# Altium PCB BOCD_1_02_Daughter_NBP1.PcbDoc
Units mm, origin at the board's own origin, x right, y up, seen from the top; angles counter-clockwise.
Board outline 69 x 80.99 mm, 2 copper layers (Top Layer, Bottom Layer); 48 components, 166 nets, 518 pads, 189 vias.
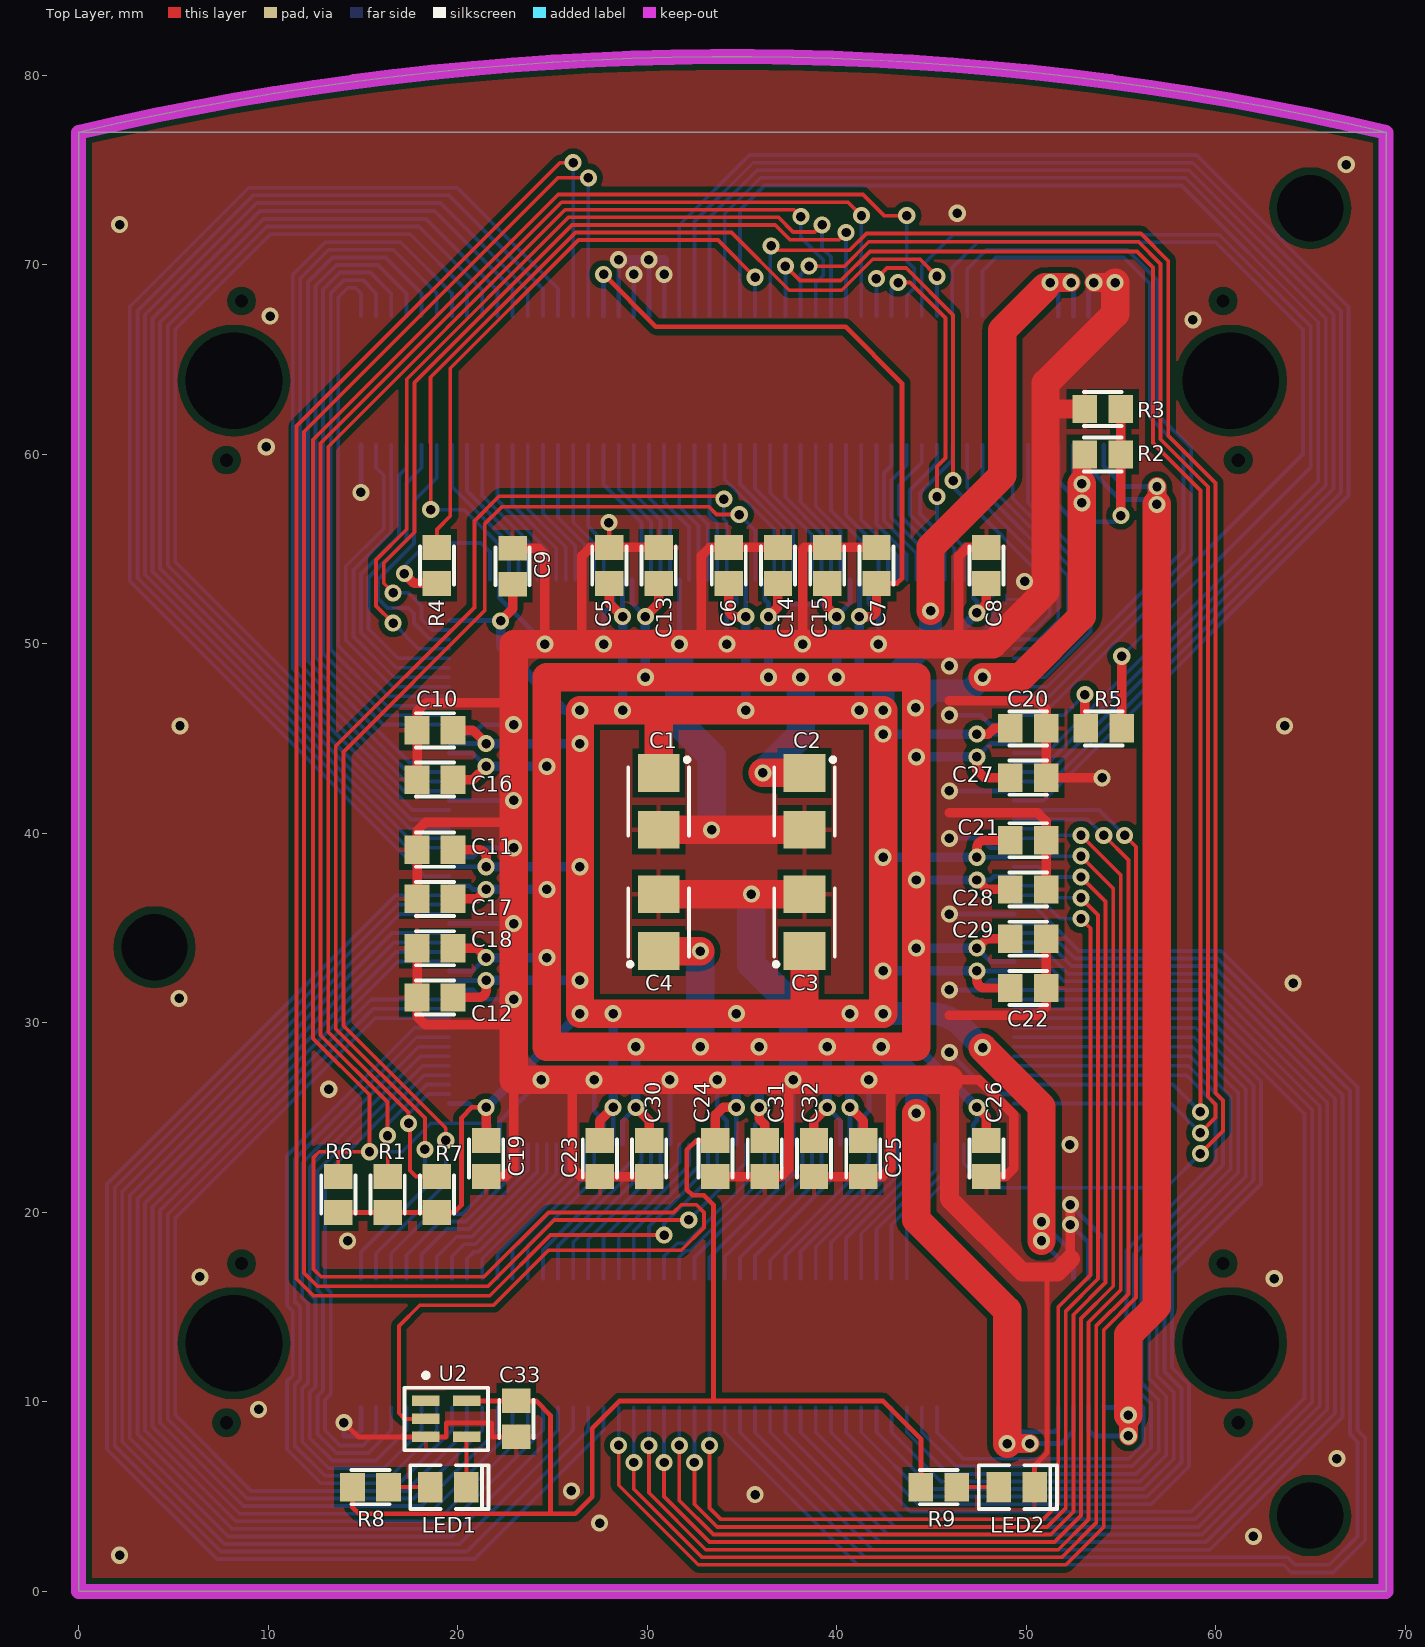
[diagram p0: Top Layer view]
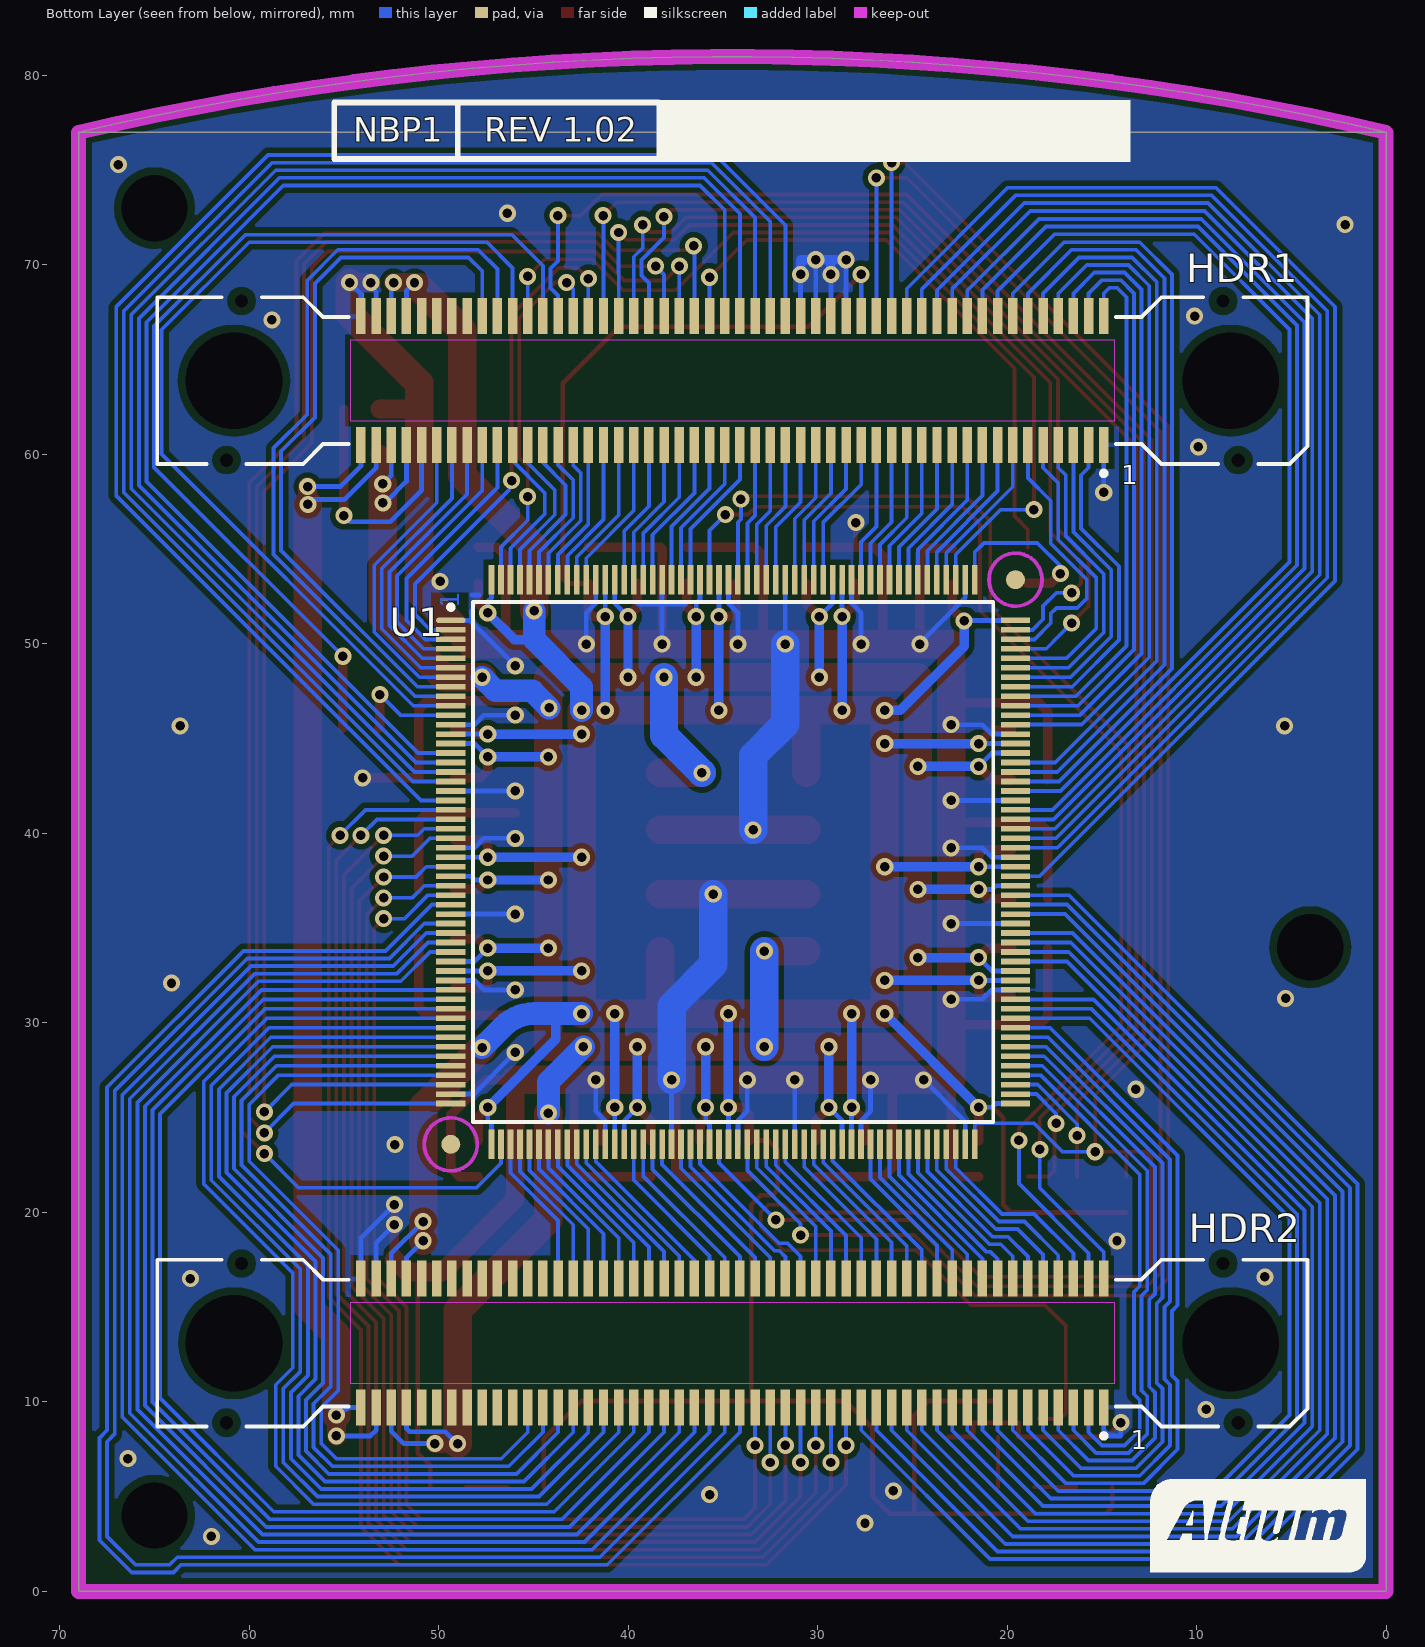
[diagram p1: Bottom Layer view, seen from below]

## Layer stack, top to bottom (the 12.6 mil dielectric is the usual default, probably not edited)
Top Layer: signal copper 0.0356
Dielectric: core 0.32, FR-4, Dk 4.8
Bottom Layer: signal copper 0.0356

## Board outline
0,0 0,77 ccw(c0.001,77) 0.001,77 cw(c34.5,-69.801) 0.001,77 69,77 69,0

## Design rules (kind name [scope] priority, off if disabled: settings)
Clearance Clearance_Unplated_Pads [PadIsPlated = 'False'] p1: gap=0.4 // Slightly larger clearance around unplated holes
Clearance Clearance_Polygons [InPolygon] p2: gap=0.3 // Larger clearance for polygons
Clearance [All] p3: gap=0.2 // General clearance
ComponentClearance [All] p1: gap=0.2 collisioncheckmode=3 verticalgap=0.254 showdistances=FALSE
FabricationTestPointUsage TestPointUsage [All] p1 off: valid=0 allowmultiple=FALSE
FabricationTestpoint Testpoint [All] p1 off: side=3 testpointundercomponent=TRUE minsize=1.016 maxsize=2.54 preferedsize=1.524 minholesize=0 maxholesize=1.016 preferedholesize=0.813 testpointgrid=0.025 allowsidetop=TRUE allowsidebottom=TRUE usegrid=TRUE gridtolerance=0
Height MaxMinHeight [All] p1: minheight=0 maxheight=25.4 prefheight=12.7
HoleSize [All] p1: absolutevalues=TRUE maxlimit=5.1 minlimit=0.4 maxpercent=80.000 minpercent=20.000
PlaneClearance [All] p1: clearance=0.5
PlaneConnect [All] p1: planeconnectstyle=Relief reliefexpansion=0.5 reliefentries=4 reliefconductorwidth=0.25 reliefairgap=0.25
PolygonConnect PolygonConnect_ID_Pads [InPadClass('Satellite ID Pads')] p1: connectstyle=NoConnect reliefconductorwidth=0.254 reliefentries=4 polygonreliefangle="90 Angle" // Prevent polygons connecting to pads identifying type of Satellite PCB
PolygonConnect [All] p2: connectstyle=Relief reliefconductorwidth=0.25 reliefentries=4 polygonreliefangle="90 Angle"
RoutingCorners [All] p1: cornerstyle=45-Degree minsetback=2.5 maxsetback=2.5
RoutingVias [All] p1: holewidth=0.5 width=0.9 viastyle="Through Hole" minholewidth=0.5 minwidth=0.9 maxholewidth=0.5 maxwidth=0.9
SilkscreenOverComponentPads [All] p1: minsilkscreentomaskgap=0.254
SolderMaskExpansion SolderMaskExpansion_Vias [IsVia] p1: expansion=-0.46
SolderMaskExpansion [All] p2: expansion=0.1
Width Width_Power [InNetClass('Power Nets')] p1: maxlimit=2.5 minlimit=0.15 preferedwidth=0.25
Width [All] p2: maxlimit=0.5 minlimit=0.2 preferedwidth=0.2
19 further rules are at their usual default settings.

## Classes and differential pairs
net class "Power Nets": 5V GND VCC VCCINT
pad class "Satellite ID Pads": HDR1-36 HDR1-38 HDR1-40 HDR1-42

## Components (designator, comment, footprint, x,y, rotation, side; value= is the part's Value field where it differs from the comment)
C1 "10uF" MCCT-B 30.608,41.692 r270 top locked
C2 "10uF" MCCT-B 38.308,41.692 r270 top locked
C3 "10uF" MCCT-B 38.308,35.292 r90 top locked
C4 "10uF" MCCT-B 30.608,35.292 r90 top locked
C5 "0.1uF" CC2012-0805 28.008,54.142 r270 top
C6 "0.1uF" CC2012-0805 34.308,54.142 r270 top
C7 "0.1uF" CC2012-0805 42.108,54.142 r270 top
C8 "0.1uF" CC2012-0805 47.908,54.142 r270 top
C9 "0.1uF" CC2012-0805 22.9,54.1 r270 top
C10 "0.1uF" CC2012-0805 18.808,45.442 r0 top
C11 "0.1uF" CC2012-0805 18.808,39.142 r0 top
C12 "0.1uF" CC2012-0805 18.808,31.342 r0 top
C13 "0.1uF" CC2012-0805 30.608,54.142 r270 top
C14 "0.1uF" CC2012-0805 36.908,54.142 r270 top
C15 "0.1uF" CC2012-0805 39.508,54.142 r270 top
C16 "0.1uF" CC2012-0805 18.808,42.842 r0 top
C17 "0.1uF" CC2012-0805 18.808,36.542 r0 top
C18 "0.1uF" CC2012-0805 18.808,33.942 r0 top
C19 "0.1uF" CC2012-0805 21.508,22.842 r270 top
C20 "0.1uF" CC2012-0805 50.108,45.542 r0 top
C21 "0.1uF" CC2012-0805 50.108,39.642 r0 top
C22 "0.1uF" CC2012-0805 50.108,31.842 r0 top
C23 "0.1uF" CC2012-0805 27.508,22.842 r270 top
C24 "0.1uF" CC2012-0805 33.608,22.842 r270 top
C25 "0.1uF" CC2012-0805 41.408,22.842 r270 top
C26 "0.1uF" CC2012-0805 47.908,22.842 r270 top
C27 "0.1uF" CC2012-0805 50.108,42.942 r0 top
C28 "0.1uF" CC2012-0805 50.108,37.042 r0 top
C29 "0.1uF" CC2012-0805 50.108,34.442 r0 top
C30 "0.1uF" CC2012-0805 30.108,22.842 r270 top
C31 "0.1uF" CC2012-0805 36.208,22.842 r270 top
C32 "0.1uF" CC2012-0805 38.808,22.842 r270 top
C33 "0.1uF" CC2012-0805 23.1,9.1 r270 top
HDR1 "54075-1009" 54075 34.5,63.9 r0 bottom locked
HDR2 "54075-1009" 54075 34.5,13.1 r0 bottom locked
LED1 "HSMG-C170" "SMD _LED" 19.5,5.5 r180 top locked
LED2 "HSMH-C170" "SMD _LED" 49.5,5.5 r180 top locked
R1 "4K7" CC2012-0805 16.308,20.942 r270 top
R2 "DO NOT INSTALL" CC2012-0805 54.05,60 r0 top
R3 "DO NOT INSTALL" CC2012-0805 54.05,62.4 r180 top
R4 "100R" CC2012-0805 18.908,54.142 r270 top
R5 "100R" CC2012-0805 54.1,45.542 r180 top
R6 "4K7" CC2012-0805 13.708,20.942 r270 top
R7 "4K7" CC2012-0805 18.908,20.942 r270 top
R8 "270R" CC2012-0805 15.4,5.5 r0 top
R9 "270R" CC2012-0805 45.4,5.5 r0 top
U1 "Spartan XC2S300E-6PQ208C" F-QFP28X28-G208/P.5N 34.458,38.492 r180 bottom locked
U2 "SN74LVC1G04DBV" SO-G5/P.95 19.4,9.1 r270 top

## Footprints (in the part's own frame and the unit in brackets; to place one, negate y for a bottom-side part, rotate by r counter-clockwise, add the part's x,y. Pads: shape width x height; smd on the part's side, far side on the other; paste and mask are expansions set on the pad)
54075 [mm] "Connector; Docking Station, Receptacle; 100 Position; Vertical"
  rect 0.5x1.9 smd: 1(-19.6,3.4) 2(-19.6,-3.4) 3(-18.8,3.4) 4(-18.8,-3.4) 5(-18,3.4) 6(-18,-3.4) 7(-17.2,3.4) 8(-17.2,-3.4) 9(-16.4,3.4) 10(-16.4,-3.4) 11(-15.6,3.4) 12(-15.6,-3.4) 13(-14.8,3.4) 14(-14.8,-3.4) 15(-14,3.4) 16(-14,-3.4) 17(-13.2,3.4) 18(-13.2,-3.4) 19(-12.4,3.4) 20(-12.4,-3.4) 21(-11.6,3.4) 22(-11.6,-3.4) 23(-10.8,3.4) 24(-10.8,-3.4) 25(-10,3.4) 26(-10,-3.4) 27(-9.2,3.4) 28(-9.2,-3.4) 29(-8.4,3.4) 30(-8.4,-3.4) 31(-7.6,3.4) 32(-7.6,-3.4) 33(-6.8,3.4) 34(-6.8,-3.4) 35(-6,3.4) 36(-6,-3.4) 37(-5.2,3.4) 38(-5.2,-3.4) 39(-4.4,3.4) 40(-4.4,-3.4) 41(-3.6,3.4) 42(-3.6,-3.4) 43(-2.8,3.4) 44(-2.8,-3.4) 45(-2,3.4) 46(-2,-3.4) 47(-1.2,3.4) 48(-1.2,-3.4) 49(-0.4,3.4) 50(-0.4,-3.4) 51(0.4,3.4) 52(0.4,-3.4) 53(1.2,3.4) 54(1.2,-3.4) 55(2,3.4) 56(2,-3.4) 57(2.8,3.4) 58(2.8,-3.4) 59(3.6,3.4) 60(3.6,-3.4) 61(4.4,3.4) 62(4.4,-3.4) 63(5.2,3.4) 64(5.2,-3.4) 65(6,3.4) 66(6,-3.4) 67(6.8,3.4) 68(6.8,-3.4) 69(7.6,3.4) 70(7.6,-3.4) 71(8.4,3.4) 72(8.4,-3.4) 73(9.2,3.4) 74(9.2,-3.4) 75(10,3.4) 76(10,-3.4) 77(10.8,3.4) 78(10.8,-3.4) 79(11.6,3.4) 80(11.6,-3.4) 81(12.4,3.4) 82(12.4,-3.4) 83(13.2,3.4) 84(13.2,-3.4) 85(14,3.4) 86(14,-3.4) 87(14.8,3.4) 88(14.8,-3.4) 89(15.6,3.4) 90(15.6,-3.4) 91(16.4,3.4) 92(16.4,-3.4) 93(17.2,3.4) 94(17.2,-3.4) 95(18,3.4) 96(18,-3.4) 97(18.8,3.4) 98(18.8,-3.4) 99(19.6,3.4) 100(19.6,-3.4)
  round 0.5 hole 0.7 unplated: MH1(-26.7,4.2) MH2(-25.9,-4.2) MH3(26.7,4.2) MH4(25.9,-4.2)
  round 4.8 hole 5.1 unplated: MH5(-26.3,0) MH6(26.3,0)
  Top Layer keep-out region: -20.15,2.15 20.15,2.15 20.15,-2.15 -20.15,-2.15
  silkscreen extent -30.35,-4.4 30.35,5.02
CC2012-0805 [mm]
  rect 1.3x1.5 smd: 1(-0.95,0) 2(0.95,0)
  silkscreen extent -1,-0.9 1,0.9
F-QFP28X28-G208/P.5N [mm]
  oval 1.55x0.3 smd: 1(-14.9,12.75)
  rect 1.55x0.3 smd: 2(-14.9,12.25) 3(-14.9,11.75) 4(-14.9,11.25) 5(-14.9,10.75) 6(-14.9,10.25) 7(-14.9,9.75) 8(-14.9,9.25) 9(-14.9,8.75) 10(-14.9,8.25) 11(-14.9,7.75) 12(-14.9,7.25) 13(-14.9,6.75) 14(-14.9,6.25) 15(-14.9,5.75) 16(-14.9,5.25) 17(-14.9,4.75) 18(-14.9,4.25) 19(-14.9,3.75) 20(-14.9,3.25) 21(-14.9,2.75) 22(-14.9,2.25) 23(-14.9,1.75) 24(-14.9,1.25) 25(-14.9,0.75) 26(-14.9,0.25) 27(-14.9,-0.25) 28(-14.9,-0.75) 29(-14.9,-1.25) 30(-14.9,-1.75) 31(-14.9,-2.25) 32(-14.9,-2.75) 33(-14.9,-3.25) 34(-14.9,-3.75) 35(-14.9,-4.25) 36(-14.9,-4.75) 37(-14.9,-5.25) 38(-14.9,-5.75) 39(-14.9,-6.25) 40(-14.9,-6.75) 41(-14.9,-7.25) 42(-14.9,-7.75) 43(-14.9,-8.25) 44(-14.9,-8.75) 45(-14.9,-9.25) 46(-14.9,-9.75) 47(-14.9,-10.25) 48(-14.9,-10.75) 49(-14.9,-11.25) 50(-14.9,-11.75) 51(-14.9,-12.25) 52(-14.9,-12.75) 105(14.9,-12.75) 106(14.9,-12.25) 107(14.9,-11.75) 108(14.9,-11.25) 109(14.9,-10.75) 110(14.9,-10.25) 111(14.9,-9.75) 112(14.9,-9.25) 113(14.9,-8.75) 114(14.9,-8.25) 115(14.9,-7.75) 116(14.9,-7.25) 117(14.9,-6.75) 118(14.9,-6.25) 119(14.9,-5.75) 120(14.9,-5.25) 121(14.9,-4.75) 122(14.9,-4.25) 123(14.9,-3.75) 124(14.9,-3.25) 125(14.9,-2.75) 126(14.9,-2.25) 127(14.9,-1.75) 128(14.9,-1.25) 129(14.9,-0.75) 130(14.9,-0.25) 131(14.9,0.25) 132(14.9,0.75) 133(14.9,1.25) 134(14.9,1.75) 135(14.9,2.25) 136(14.9,2.75) 137(14.9,3.25) 138(14.9,3.75) 139(14.9,4.25) 140(14.9,4.75) 141(14.9,5.25) 142(14.9,5.75) 143(14.9,6.25) 144(14.9,6.75) 145(14.9,7.25) 146(14.9,7.75) 147(14.9,8.25) 148(14.9,8.75) 149(14.9,9.25) 150(14.9,9.75) 151(14.9,10.25) 152(14.9,10.75) 153(14.9,11.25) 154(14.9,11.75) 155(14.9,12.25) 156(14.9,12.75)
  rect 0.3x1.55 smd: 53(-12.75,-14.9) 54(-12.25,-14.9) 55(-11.75,-14.9) 56(-11.25,-14.9) 57(-10.75,-14.9) 58(-10.25,-14.9) 59(-9.75,-14.9) 60(-9.25,-14.9) 61(-8.75,-14.9) 62(-8.25,-14.9) 63(-7.75,-14.9) 64(-7.25,-14.9) 65(-6.75,-14.9) 66(-6.25,-14.9) 67(-5.75,-14.9) 68(-5.25,-14.9) 69(-4.75,-14.9) 70(-4.25,-14.9) 71(-3.75,-14.9) 72(-3.25,-14.9) 73(-2.75,-14.9) 74(-2.25,-14.9) 75(-1.75,-14.9) 76(-1.25,-14.9) 77(-0.75,-14.9) 78(-0.25,-14.9) 79(0.25,-14.9) 80(0.75,-14.9) 81(1.25,-14.9) 82(1.75,-14.9) 83(2.25,-14.9) 84(2.75,-14.9) 85(3.25,-14.9) 86(3.75,-14.9) 87(4.25,-14.9) 88(4.75,-14.9) 89(5.25,-14.9) 90(5.75,-14.9) 91(6.25,-14.9) 92(6.75,-14.9) 93(7.25,-14.9) 94(7.75,-14.9) 95(8.25,-14.9) 96(8.75,-14.9) 97(9.25,-14.9) 98(9.75,-14.9) 99(10.25,-14.9) 100(10.75,-14.9) 101(11.25,-14.9) 102(11.75,-14.9) 103(12.25,-14.9) 104(12.75,-14.9) 157(12.75,14.9) 158(12.25,14.9) 159(11.75,14.9) 160(11.25,14.9) 161(10.75,14.9) 162(10.25,14.9) 163(9.75,14.9) 164(9.25,14.9) 165(8.75,14.9) 166(8.25,14.9) 167(7.75,14.9) 168(7.25,14.9) 169(6.75,14.9) 170(6.25,14.9) 171(5.75,14.9) 172(5.25,14.9) 173(4.75,14.9) 174(4.25,14.9) 175(3.75,14.9) 176(3.25,14.9) 177(2.75,14.9) 178(2.25,14.9) 179(1.75,14.9) 180(1.25,14.9) 181(0.75,14.9) 182(0.25,14.9) 183(-0.25,14.9) 184(-0.75,14.9) 185(-1.25,14.9) 186(-1.75,14.9) 187(-2.25,14.9) 188(-2.75,14.9) 189(-3.25,14.9) 190(-3.75,14.9) 191(-4.25,14.9) 192(-4.75,14.9) 193(-5.25,14.9) 194(-5.75,14.9) 195(-6.25,14.9) 196(-6.75,14.9) 197(-7.25,14.9) 198(-7.75,14.9) 199(-8.25,14.9) 200(-8.75,14.9) 201(-9.25,14.9) 202(-9.75,14.9) 203(-10.25,14.9) 204(-10.75,14.9) 205(-11.25,14.9) 206(-11.75,14.9) 207(-12.25,14.9) 208(-12.75,14.9)
  round 1 smd paste-0.51 mask+1: FID1(-14.9,-14.9) FID2(14.9,14.9)
  Top Layer keep-out circle w0.2: c-14.9,-14.9 r1.4
  Top Layer keep-out circle w0.2: c14.9,14.9 r1.4
  silkscreen extent -15.03,-13.72 13.73,13.73
MCCT-B [mm]
  rect 2x2.2 smd: 1(-1.5,0) 2(1.5,0)
  silkscreen extent -2.3,-1.6 1.8,1.6
"SMD _LED" [mm]
  rect 1.3x1.6 smd: 1(0.95,0) 2(-0.95,0)
  silkscreen extent -2.13,-1.15 2,1.15
SO-G5/P.95 [mm]
  rect 0.55x1.45 smd: 1(-0.95,-1.075) 2(0,-1.075) 3(0.95,-1.075) 4(0.95,1.075) 5(-0.95,1.075)
  silkscreen extent -2.42,-2.2 1.65,2.2

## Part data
C1 C2 C3 C4: library part CAP_POLAR, "Polar Capacitor"
C5 C6 C7 C8 C9 C10 C11 C12 C13 C14 C15 C16 C17 C18 C19 C20 C21 C22 C23 C24 C25 C26 C27 C28 C29 C30 C31 C32 C33: library part CAP, "Capacitor"
HDR1 HDR2: "Board-to-Board, Docking Station, 0.80mm (.031\") Pitch, Shielded Receptacle, Vertical, Ultra Low Profile, SMT"
LED1 LED2: library part HSMX-C670, "Typical RED GaAs SMD LED Agilent make"
R1 R2 R3 R4 R5 R6 R7 R8 R9: library part RES, "Resistor"
U1: library part XC2S300E-6PQ208I, "1.8V Field-Programmable Gate Array"
U2: library part SN74AHC1G04DBVR

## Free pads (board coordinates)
  round 3.2 hole 3.5 unplated: LP(4,34) LP(65,4) LP(65,73)

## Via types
v1: diameter 0.9, hole 0.5, Top Layer to Bottom Layer, 189 vias

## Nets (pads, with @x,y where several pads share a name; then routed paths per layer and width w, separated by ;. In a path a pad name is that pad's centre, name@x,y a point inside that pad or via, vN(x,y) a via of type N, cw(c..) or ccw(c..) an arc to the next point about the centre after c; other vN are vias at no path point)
5V: HDR1.97 HDR1.99 HDR2.97 HDR2.99 | length 65.5
  Top Layer w1: v1(55.4,8.2) v1(55.4,9.3) ; v1(56.9,57.364) v1(56.911,58.304)
  Top Layer w1.5: v1(55.4,9.3) 55.4,13.538 56.9,15.038 v1(56.9,57.364)
  Bottom Layer w0.25: HDR2.97 53.3,8.5 53.6,8.2 v1(55.4,8.2) ; HDR1.97 53.3,59.3 54.982,57.618 56.646,57.618 v1(56.9,57.364) ; HDR2.99 54.7,9.7 v1(55.4,9.3) ; HDR1.99 54.1,59.375 54.77,58.718 55.184,58.304 v1(56.911,58.304)
AUDIO_SPI_CSN: HDR1.11 U1.154 | length 14.3
  Bottom Layer w0.2: HDR1.11 18.9,58.761 17.7,57.561 17.7,55.3 15.8,53.4 15.8,52.4 16.3,51.9 17.4,51.9 17.7,51.6 17.7,51.1 18.558,50.242 U1.154
BLUE0: HDR1.14 U1.139 | length 42.9
  Bottom Layer w0.2: U1.139 17.258,42.742 11.3,48.7 11.3,69.5 13,71.2 17,71.2 19.7,68.5 HDR1.14
BLUE1: HDR1.16 U1.138 | length 51.8
  Bottom Layer w0.2: U1.138 17.177,42.242 5.1,54.319 5.1,66.6 10.125,71.625 17.5,71.625 20.5,68.625 HDR1.16
BOC_CTS: HDR1.13 U1.160 | length 8.6
  Bottom Layer w0.2: HDR1.13 19.7,58.3 23.208,54.792 U1.160
BOC_RTS: HDR1.17 U1.162 | length 8.3
  Bottom Layer w0.2: HDR1.17 21.3,57.831 24.208,54.923 U1.162
BOC_RX: HDR1.19 U1.163 | length 8.2
  Bottom Layer w0.2: HDR1.19 22.1,57.597 24.708,54.989 U1.163
BOC_TX: HDR1.15 U1.161 | length 8.4
  Bottom Layer w0.2: HDR1.15 20.5,58.065 23.708,54.857 U1.161
BUZZER: HDR2.24 U1.93 | length 8.5
  Bottom Layer w0.2: HDR2.24 23.7,18.26 27.208,21.768 U1.93
CAN_RXD: HDR1.4 U1.147 | length 30.5
  Bottom Layer w0.2: HDR1.4 15.7,68.5 15,69.2 14,69.2 13.3,68.5 13.3,49.7 16.258,46.742 U1.147
CAN_TXD: HDR1.2 U1.148 | length 28.1
  Bottom Layer w0.2: HDR1.2 14.9,68.5 14.6,68.8 14.2,68.8 13.7,68.3 13.7,49.9 16.358,47.242 U1.148
FPGA_CCLK: HDR1.66 U1.155 | length 47.3
  Top Layer w0.2: v1(16.6,52.7) 16.1,53.2 16.1,54.272 17.719,55.891 17.719,63.79 26.044,72.115 36.768,72.115 37.549,71.334 40.122,71.334 v1(40.503,71.715)
  Bottom Layer w0.2: v1(16.6,52.7) 17.4,52.7 18.1,52 18.1,51.3 18.658,50.742 U1.155 ; HDR1.66 v1(40.503,71.715)
FPGA_CLK: HDR2.2 U1.182 | length 64.5
  Top Layer w0.2: v1(18.275,23.325) 18.275,24.979 13.571,29.683 13.571,44.606 20.894,51.928 20.894,56.496 22.197,57.8 33.895,57.8 v1(34.051,57.643)
  Bottom Layer w0.2: HDR2.2 14.9,17.918 18.275,21.293 v1(18.275,23.325) ; v1(34.051,57.643) 34.051,56.577 34.208,56.42 U1.182
FPGA_CLK_1: HDR1.30 U1.80 | length 100.5
  Top Layer w0.2: v1(26.1,75.4) 25.4,75.4 11.5,61.5 11.5,16.5 12.4,15.6 21.7,15.6 24.9,18.8 v1(30.9,18.8)
  Bottom Layer w0.2: HDR1.30 v1(26.1,75.4) ; v1(30.9,18.8) 30.9,19.4 33.708,22.208 U1.80
FPGA_CLK_2: HDR1.32 U1.77 | length 99.5
  Top Layer w0.2: v1(26.9,74.6) 25.3,74.6 11.9,61.2 11.9,16.8 12.6,16.1 21.6,16.1 25.1,19.6 v1(32.2,19.6)
  Bottom Layer w0.2: HDR1.32 v1(26.9,74.6) ; v1(32.2,19.6) 35.208,22.608 U1.77
FPGA_DIN: HDR1.64 U1.153 | length 48.4
  Top Layer w0.2: v1(16.6,51.1) 15.7,52 15.7,54.438 17.312,56.05 17.312,63.968 25.86,72.515 36.934,72.515 37.709,71.74 38.852,71.74 v1(39.233,72.121)
  Bottom Layer w0.2: v1(16.6,51.1) 17.933,49.742 U1.153 ; v1(39.233,72.121) 39.233,70.9 39.7,70.433 HDR1.64
FPGA_DONE: HDR1.74 R6.1 U1.104 U2.2 | length 147.6
  Top Layer w0.2: 13.7,23.2 R6.1 ; U2.2 17.2,9.1 16.9,9.4 16.9,14 18,15.1 21.9,15.1 24.8,18 31.8,18 33,19.2 33,20 32.6,20.4 31.8,20.4 31.4,20 24.8,20 21.4,16.6 12.8,16.6 12.4,17 12.4,22.9 12.7,23.2 v1(15.35,23.2) 15.35,26.207 12.371,29.186 12.371,60.779 25.313,73.722 41.392,73.722 42.509,72.604 v1(43.703,72.604)
  Bottom Layer w0.2: v1(15.35,23.2) 17.083,23.2 18.586,24.703 21.597,24.703 21.708,24.592 U1.104 ; HDR1.74 43.7,68.385 44.1,68.785 44.1,69.819 43.703,70.216 v1(43.703,72.604)
FPGA_INIT: HDR1.68 R1.1 U1.107 | length 84.6
  Top Layer w0.2: v1@16.3,24.075 16.3,25.823 12.771,29.351 12.771,60.595 25.491,73.315 40.604,73.315 v1(41.315,72.604) ; R1.1 v1@16.308,24.05
  Bottom Layer w0.2: v1(16.3,24.05) 16.3,24.656 18.387,26.742 U1.107 ; HDR1.68 41.3,72.385 v1@41.519,72.604 ; v1@41.315,72.4 v1(41.315,72.604)
FPGA_M0: HDR1.60 U1.52 | length 80.3
  Top Layer w0.2: v1(38.547,69.937) 40.413,69.937 41.701,71.226 55.927,71.226 57.1,70.053 57.1,60.8 59.6,58.3 59.6,26.1 60,25.7 60,25 v1(59.2,24.2)
  Bottom Layer w0.2: HDR1.60 38.1,69.49 v1(38.547,69.937) ; U1.52 57.658,25.742 v1(59.2,24.2)
FPGA_M1: HDR1.58 U1.50 | length 79.4
  Top Layer w0.2: v1(37.3,69.939) 38.064,69.175 40.216,69.175 41.756,70.715 55.852,70.715 56.7,69.867 56.7,60.6 59.2,58.1 v1(59.2,25.3)
  Bottom Layer w0.2: HDR1.58 v1(37.3,69.939) ; U1.50 57.758,26.742 v1(59.2,25.3)
FPGA_M2: HDR1.56 U1.54 | length 89.9
  Top Layer w0.2: v1(36.54,71.004) 36.286,70.775 40.685,70.775 41.574,71.664 56.059,71.664 57.5,70.223 57.5,61 60,58.5 60,26.3 60.4,25.9 60.4,24.3 v1(59.2,23.1)
  Bottom Layer w0.2: HDR1.56 36.5,70.964 v1(36.54,71.004) v1@36.5,70.908 ; U1.54 46.708,22.592 48,21.3 57.4,21.3 v1(59.2,23.1)
FPGA_PROGRAM: HDR1.62 R7.1 U1.106 | length 80.9
  Top Layer w0.2: R7.1 17.808,21.892 17.492,22.208 17.492,24.742 v1(17.414,24.7) 17.414,25.274 13.171,29.517 13.171,60.411 25.675,72.915 37.753,72.915 v1(38.115,72.553)
  Bottom Layer w0.2: v1(17.414,24.7) 17.414,25.204 18.452,26.242 U1.106 ; v1(38.115,72.553) 38.115,71.452 39.3,70.267 39.3,69.446 38.9,69.046 HDR1.62
FPGA_TCK: HDR1.72 U1.207 | length 19.8
  Top Layer w0.2: v1(43.246,69.073) 43.874,69.073 45.75,67.197 45.75,59.817 45.3,59.367 v1(45.3,57.775)
  Bottom Layer w0.2: HDR1.72 42.9,68.728 v1(43.246,69.073) ; v1(45.3,57.775) 45.3,56.526 46.708,55.118 ; U1.207 46.712,55.118
FPGA_TDI: HDR1.78 U1.159 | length 47.7
  Top Layer w0.2: v1(18.582,57.085) 18.575,64.075 25.187,70.687 26.215,71.715 34.457,71.715 37.505,68.667 40.274,68.667 41.909,70.302 44.398,70.302 v1(45.3,69.4)
  Bottom Layer w0.2: v1(18.582,57.085) 20.349,57.085 22.708,54.726 U1.159 ; HDR1.78 v1(45.3,69.4)
FPGA_TDO: HDR1.54 R4.1 | length 31.5
  Top Layer w0.2: R4.1 18.908,56.043 19.613,56.749 19.613,64.548 26.381,71.315 33.74,71.315 v1(35.702,69.353)
  Bottom Layer w0.2: HDR1.54 v1(35.702,69.353)
FPGA_TDO#: R4.2 U1.157 | length 9
  Top Layer w0.5: v1(17.185,53.706) 17.699,53.192 R4.2
  Bottom Layer w0.2: v1(17.185,53.706) 17.185,54.113 18.405,55.332 21.224,55.332 21.708,54.848 U1.157
FPGA_TMS: HDR1.70 U1.2 | length 27.4
  Top Layer w0.2: v1(42.103,69.277) 42.661,69.835 43.678,69.835 46.15,67.363 v1(46.15,58.625)
  Bottom Layer w0.2: HDR1.70 v1(42.103,69.277) v1@42.1,69.274 ; v1(46.15,58.625) 46.27,58.15 51.25,53.17 51.25,51.55 50.442,50.742 U1.2
GND: C1.2 C2.2 C3.2 C4.2 C5.1 C6.1 C7.1 C8.1 C9.1 C10.1 C11.1 C12.1 C13.1 C14.1 C15.1 C16.1 C17.1 C18.1 C19.2 C20.2 C21.2 C22.2 C23.2 C24.2 C25.2 C26.2 C27.2 C28.2 C29.2 C30.2 C31.2 C32.2 C33.2 HDR1.1 HDR1.36 HDR1.38 HDR1.40 HDR1.42 HDR1.98 HDR1.100 HDR2.1 HDR2.98 HDR2.100 LED2.2 R3.2 U1.1 U1.12 U1.19 U1.25 U1.32 U1.39 U1.51 U1.65 U1.72 U1.79 U1.85 U1.92 U1.103 U1.117 U1.124 U1.131 U1.137 U1.144 U1.158 U1.170 U1.177 U1.183 U1.190 U1.197 U2.3 | length 434.5
  Top Layer w0.25: v1(14,8.9) 14.75,8.15 19.4,8.15 19.4,8.9 21.8,8.9 21.8,8.15 C33.2 ; v1(27.98,56.399) 28.008,56.371 C5.1 ; LED2.2 50.45,6.65 51.1,7.3 51.1,16.85
  Top Layer w0.5: C18.1 17.858,30.342 18.308,29.892 22.958,29.892 ; C17.1 17.858,40.142 18.308,40.592 22.958,40.592 ; C16.1 17.858,46.442 18.308,46.892 22.958,46.892 ; C19.2 22.508,21.892 22.958,22.342 22.958,26.992 ; C9.1 24.277,55.05 24.602,54.725 v1(24.602,49.992) ; 26.058,26.992 26.058,22.342 26.508,21.892 C30.2 ; 26.558,49.992 26.558,54.642 27.008,55.092 C13.1 ; 32.858,49.992 32.858,54.642 33.308,55.092 C14.1 ; C24.2 C31.2 37.06,21.892 37.48,22.312 37.48,26.764 v1(37.708,26.992) ; v1(38.208,49.992) 38.208,55.008 38.292,55.092 C7.1 ; C32.2 42.408,21.892 42.858,22.342 42.858,26.992 ; 45.958,26.992 47.508,26.992 49.358,25.142 49.358,22.342 48.908,21.892 C26.2 ; 45.958,30.392 50.608,30.392 51.058,30.842 C29.2 ; 45.958,41.092 50.608,41.092 51.058,40.642 C28.2 ; 45.958,46.992 50.608,46.992 51.058,46.542 C27.2 54.01,42.942 v1(54.015,42.937) ; 46.458,49.992 46.458,54.642 46.908,55.092 C8.1 ; 52.339,17.537 v1(52.339,20.407)
  Top Layer w1: 45.958,26.992 45.958,20.707 49.815,16.85 51.652,16.85 52.339,17.537 ; 51.069,62.4 R3.2 ; v1(53.575,69.075) v1(54.7,69.075)
  Top Layer w1.5: C4.2 C3.2 ; C1.2 C2.2 ; 45.958,26.992 22.958,26.992 22.958,49.992 48.25,49.992 51.025,52.767 51.025,63.75 54.701,67.418 v1(54.7,69.075)
  Bottom Layer w0.25: v1(14,8.9) 14,8.2 14.6,8.2 14.9,8.5 HDR2.1 ; v1(14.9,58) HDR1.1 ; U1.117 20.808,31.742 21.308,31.242 v1(22.958,31.242) ; U1.124 v1(22.958,35.242) ; U1.131 20.808,38.742 21.308,39.242 v1(22.958,39.242) ; U1.137 v1(22.958,41.742) ; U1.144 20.808,45.242 21.308,45.742 v1(22.958,45.742) ; U1.103 22.208,24.792 v1(24.408,26.992) ; U1.158 22.208,52.436 v1@24.602,50.042 ; v1(27.208,26.992) 27.208,25.342 27.708,24.842 U1.92 ; v1(27.708,49.992) 27.708,51.642 28.208,52.142 U1.170 ; HDR1.36 28.5,70.1 v1(28.5,70.275) ; HDR1.38 v1(29.3,69.5) ; HDR1.40 30.1,70.1 v1(30.1,70.275) ; HDR1.42 v1(30.9,69.5) ; U1.85 v1(31.208,26.992) ; v1(31.708,49.992) U1.177 ; v1(33.708,26.992) 33.708,25.342 34.208,24.842 U1.79 ; v1(34.208,49.992) 34.208,51.642 34.708,52.142 U1.183 ; 36.972,52.106 39.461,52.106 ; U1.72 v1(37.708,26.992) ; v1(38.208,49.992) U1.190 ; U1.65 41.208,24.842 41.708,25.342 v1(41.708,26.992) ; U1.197 41.708,52.142 42.208,51.642 v1(42.208,49.992) ; v1(45.958,28.442) 48.158,26.242 U1.51 ; v1(45.958,31.742) 47.608,31.742 48.108,32.242 U1.39 ; v1(45.958,35.742) U1.32 ; v1(45.958,39.742) 47.608,39.742 48.108,39.242 U1.25 ; v1(45.958,42.242) U1.19 ; v1(45.958,46.242) 47.608,46.242 48.108,45.742 U1.12 ; v1(45.958,48.842) 48.278,51.163 48.358,51.242 U1.1 ; 47.869,52.589 48.25,52.589 ; 48.275,51.166 48.275,51.751 ; v1(52.339,19.357) 53.3,18.396 HDR2.98 ; v1(52.339,20.407) 54.1,18.646 HDR2.100 ; HDR1.98 53.3,68.575 53.687,68.962 53.75,69.025 v1(53.575,69.075) ; HDR1.100 54.1,68.475 v1(54.7,69.075)
  Bottom Layer w0.5: v1(28.5,70.275) 29.3,70.275 ; v1@29.275,69.5 v1@29.325,69.5 ; v1(29.3,69.5) 29.3,70.275 ; v1(30.9,69.5) 30.9,70.275 v1(30.1,70.275) 29.3,70.275
  Bottom Layer w1.5: v1(31.708,49.992) 31.708,45.792 33.408,44.092 v1(33.408,40.192) ; v1(35.508,36.792) 35.508,33.092 37.708,30.892 v1(37.708,26.992)
  other v1: 2.159,1.905 62,2.9 27.5,3.6 35.7,5.1 26,5.3 66.4,7 9.5,9.6 63.1,16.5 6.4,16.6 14.2,18.5 52.314,23.582 13.2,26.5 5.3,31.3 64.1,32.1 5.349,45.68 63.642,45.68 49.926,53.3 9.9,60.4 58.8,67.1 10.1,67.3 2.159,72.136 46.37,72.731 66.9,75.3
GREEN0: HDR1.10 U1.141 | length 38.2
  Bottom Layer w0.2: HDR1.10 18.1,68.5 16.2,70.4 13.4,70.4 12.1,69.1 12.1,49.1 17.458,43.742 U1.141
GREEN1: HDR1.12 U1.140 | length 40.6
  Bottom Layer w0.2: HDR1.12 18.9,68.5 16.6,70.8 13.2,70.8 11.7,69.3 11.7,48.9 17.358,43.242 U1.140
HDRIVE: HDR1.18 U1.136 | length 54.4
  Bottom Layer w0.2: U1.136 17.611,41.242 4.7,54.153 4.7,66.8 9.925,72.025 17.95,72.025 21.3,68.675 HDR1.18
IO0: HDR2.7 U1.110 | length 31.8
  Bottom Layer w0.2: HDR2.7 17.3,8.5 15.7,6.9 13.4,6.9 12.2,8.1 12.2,10.5 12.5,10.8 12.5,15.4 12.2,15.7 12.2,22.4 18.042,28.242 U1.110
IO1: HDR2.9 U1.111 | length 34.2
  Bottom Layer w0.2: HDR2.9 18.1,8.5 16.1,6.5 13.2,6.5 11.8,7.9 11.8,10.7 12.1,11 12.1,15.2 11.8,15.5 11.8,22.6 17.942,28.742 U1.111
IO2: HDR2.11 U1.112 | length 36.5
  Bottom Layer w0.2: HDR2.11 18.9,8.5 16.5,6.1 13,6.1 11.4,7.7 11.4,10.9 11.7,11.2 11.7,15 11.4,15.3 11.4,22.8 17.842,29.242 U1.112
IO3: HDR2.13 U1.113 | length 38.9
  Bottom Layer w0.2: U1.113 17.742,29.742 11,23 11,15.1 11.3,14.8 11.3,11.4 11,11.1 11,7.5 12.8,5.7 16.9,5.7 19.7,8.5 HDR2.13
IO4: HDR2.15 U1.114 | length 48.8
  Bottom Layer w0.2: U1.114 15.642,30.242 5.1,19.7 5.1,9.3 9.1,5.3 17.3,5.3 20.5,8.5 HDR2.15
IO5: HDR2.17 U1.115 | length 51.2
  Bottom Layer w0.2: U1.115 15.542,30.742 4.7,19.9 4.7,9.1 8.9,4.9 17.7,4.9 21.3,8.5 HDR2.17
IO6: HDR2.19 U1.116 | length 53.6
  Bottom Layer w0.2: U1.116 15.442,31.242 4.3,20.1 4.3,8.9 8.7,4.5 18.1,4.5 22.1,8.5 HDR2.19
IO7: HDR2.21 U1.120 | length 56.5
  Bottom Layer w0.2: U1.120 16.842,33.242 3.9,20.3 3.9,8.7 8.5,4.1 18.5,4.1 22.9,8.5 HDR2.21
IO8: HDR2.23 U1.121 | length 58.9
  Bottom Layer w0.2: U1.121 16.742,33.742 3.5,20.5 3.5,8.5 8.3,3.7 18.9,3.7 23.7,8.5 HDR2.23
IO9: HDR2.25 U1.122 | length 61.3
  Bottom Layer w0.2: U1.122 16.642,34.242 3.1,20.7 3.1,8.3 8.1,3.3 19.3,3.3 24.5,8.5 HDR2.25
IO10: HDR2.27 U1.123 | length 63.7
  Bottom Layer w0.2: U1.123 16.542,34.742 2.7,20.9 2.7,8.1 7.9,2.9 19.7,2.9 25.3,8.5 HDR2.27
IO11: HDR2.29 U1.125 | length 66.2
  Bottom Layer w0.2: U1.125 16.942,35.742 2.3,21.1 2.3,7.9 7.7,2.5 20.1,2.5 26.1,8.5 HDR2.29
IO12: HDR2.31 U1.126 | length 68.6
  Bottom Layer w0.2: U1.126 16.842,36.242 1.9,21.3 1.9,7.7 7.5,2.1 20.5,2.1 26.9,8.5 HDR2.31
IO13: HDR2.33 U1.127 | length 71
  Bottom Layer w0.2: U1.127 16.742,36.742 1.5,21.5 1.5,7.5 7.3,1.7 20.9,1.7 27.7,8.5 HDR2.33
IO14: HDR2.35 U1.21 | length 76.1
  Top Layer w0.2: v1(28.5,7.7) 28.5,5.6 32.7,1.4 52.1,1.4 54.1,3.4 54.1,13.8 55.8,15.5 55.8,39.3 v1(55.2,39.9)
  Bottom Layer w0.2: v1(28.5,7.7) HDR2.35 ; U1.21 53.858,41.242 v1(55.2,39.9)
IO15: HDR2.37 U1.22 | length 73.6
  Top Layer w0.2: v1(29.3,6.8) 29.3,5.4 32.9,1.8 51.9,1.8 53.7,3.6 53.7,14 55.4,15.7 55.4,38.6 v1(54.1,39.9)
  Bottom Layer w0.2: v1(29.3,6.8) HDR2.37 ; U1.22 53.258,40.742 v1(54.1,39.9)
IO16: HDR2.39 U1.23 | length 71
  Top Layer w0.2: v1(30.1,7.7) 30.1,5.2 33.1,2.2 51.7,2.2 53.3,3.8 53.3,14.2 55,15.9 55,37.8 v1(52.9,39.9)
  Bottom Layer w0.2: v1(30.1,7.7) HDR2.39 ; U1.23 50.758,40.242 51.1,39.9 v1(52.9,39.9)
IO17: HDR2.41 U1.24 | length 68.4
  Top Layer w0.2: v1(30.9,6.8) 30.9,5 33.3,2.6 51.5,2.6 52.9,4 52.9,14.4 54.6,16.1 54.6,37.1 v1(52.9,38.8)
  Bottom Layer w0.2: v1(30.9,6.8) HDR2.41 ; U1.24 50.458,39.742 51.4,38.8 v1(52.9,38.8)
IO18: HDR2.43 U1.27 | length 65.5
  Top Layer w0.2: v1(31.7,7.7) 31.7,4.8 33.5,3 51.3,3 52.5,4.2 52.5,14.6 54.2,16.3 54.2,36.4 v1(52.9,37.7)
  Bottom Layer w0.2: v1(31.7,7.7) HDR2.43 ; U1.27 50.658,38.242 51.2,37.7 v1(52.9,37.7)
IO19: HDR2.45 U1.29 | length 62.7
  Top Layer w0.2: v1(32.5,6.8) 32.5,4.6 33.7,3.4 51.1,3.4 52.1,4.4 52.1,14.8 53.8,16.5 53.8,35.7 v1(52.9,36.6)
  Bottom Layer w0.2: v1(32.5,6.8) HDR2.45 ; U1.29 50.758,37.242 51.4,36.6 v1(52.9,36.6)
IO20: HDR2.47 U1.30 | length 60.1
  Top Layer w0.2: v1(33.3,7.7) 33.3,4.4 33.9,3.8 50.9,3.8 51.7,4.6 51.7,15 53.4,16.7 53.4,35 v1(52.9,35.5)
  Bottom Layer w0.2: v1(33.3,7.7) HDR2.47 ; U1.30 50.558,36.742 51.8,35.5 v1(52.9,35.5)
IO21: HDR2.49 U1.31 | length 85.1
  Bottom Layer w0.2: HDR2.49 34.1,8.4 41.1,1.4 63.6,1.4 64,1 66.2,1 67.9,2.7 67.9,8.1 67.5,8.5 67.5,26.6 60.3,33.8 52.8,33.8 50.358,36.242 U1.31
IO22: HDR2.51 U1.33 | length 82.5
  Bottom Layer w0.2: HDR2.51 34.9,8.4 41.5,1.8 63.8,1.8 64.2,1.4 66,1.4 67.5,2.9 67.5,7.9 67.1,8.3 67.1,26.4 60.1,33.4 52.6,33.4 50.758,35.242 U1.33
IO23: HDR2.53 U1.34 | length 75.6
  Bottom Layer w0.2: HDR2.53 35.7,8.4 41.9,2.2 59.7,2.2 66.7,9.2 66.7,26.2 59.9,33 52.4,33 50.658,34.742 U1.34
IO24: HDR2.55 U1.35 | length 73.3
  Bottom Layer w0.2: HDR2.55 36.5,8.4 42.3,2.6 59.5,2.6 66.3,9.4 66.3,26 59.7,32.6 52.2,32.6 50.558,34.242 U1.35
IO25: HDR2.57 U1.36 | length 70.9
  Bottom Layer w0.2: HDR2.57 37.3,8.4 42.7,3 59.3,3 65.9,9.6 65.9,25.8 59.5,32.2 52,32.2 50.458,33.742 U1.36
IO26: HDR2.59 U1.40 | length 67.9
  Bottom Layer w0.2: HDR2.59 38.1,8.4 43.1,3.4 59.1,3.4 65.5,9.8 65.5,25.6 59.358,31.742 U1.40
IO27: HDR2.61 U1.41 | length 65.5
  Bottom Layer w0.2: HDR2.61 38.9,8.4 43.5,3.8 58.9,3.8 65.1,10 65.1,25.4 59.258,31.242 U1.41
IO28: HDR2.63 U1.42 | length 63.2
  Bottom Layer w0.2: HDR2.63 39.7,8.4 43.9,4.2 58.7,4.2 64.7,10.2 64.7,25.2 59.158,30.742 U1.42
IO29: HDR2.65 U1.43 | length 58.8
  Bottom Layer w0.2: HDR2.65 40.5,8.4 44.3,4.6 56.6,4.6 58.6,6.6 58.6,10.9 57.7,11.8 57.7,16.8 62.4,21.5 62.4,26.9 59.058,30.242 U1.43
IO30: HDR2.67 U1.44 | length 56.5
  Bottom Layer w0.2: HDR2.67 41.3,8.4 44.7,5 56.4,5 58.2,6.8 58.2,10.7 57.3,11.6 57.3,17 62,21.7 62,26.7 58.958,29.742 U1.44
IO31: HDR2.69 U1.45 | length 54.1
  Bottom Layer w0.2: HDR2.69 42.1,8.4 45.1,5.4 56.2,5.4 57.8,7 57.8,10.5 56.9,11.4 56.9,17.2 61.6,21.9 61.6,26.5 58.858,29.242 U1.45
IO32: HDR2.71 U1.46 | length 51.7
  Bottom Layer w0.2: HDR2.71 42.9,8.4 45.5,5.8 56,5.8 57.4,7.2 57.4,10.3 56.5,11.2 56.5,17.4 61.2,22.1 61.2,26.3 58.758,28.742 U1.46
IO33: HDR2.73 U1.47 | length 49.4
  Bottom Layer w0.2: HDR2.73 43.7,8.4 45.9,6.2 55.8,6.2 57,7.4 57,10.1 56.1,11 56.1,17.6 60.8,22.3 60.8,26.1 58.658,28.242 U1.47
IO34: HDR2.75 U1.48 | length 47
  Bottom Layer w0.2: HDR2.75 44.5,8.4 46.3,6.6 55.6,6.6 56.6,7.6 56.6,9.9 55.7,10.8 55.7,17.8 60.4,22.5 60.4,25.9 58.558,27.742 U1.48
IO35: HDR2.77 U1.49 | length 44.6
  Bottom Layer w0.2: HDR2.77 45.3,8.4 46.7,7 55.4,7 56.2,7.8 56.2,9.7 55.3,10.6 55.3,18 60,22.7 60,25.7 58.458,27.242 U1.49
JIOA0: HDR1.3 U1.149 | length 17.8
  Bottom Layer w0.2: HDR1.3 15.7,59.3 16.1,58.9 16.1,56.1 14.1,54.1 14.1,50.2 16.558,47.742 U1.149
JIOA1: HDR1.5 U1.150 | length 16.9
  Bottom Layer w0.2: HDR1.5 16.5,55.9 14.5,53.9 14.5,50.4 16.658,48.242 U1.150
JIOA2: HDR1.7 U1.151 | length 16.3
  Bottom Layer w0.2: HDR1.7 17.3,59.3 16.9,58.9 16.9,55.7 14.9,53.7 14.9,50.6 16.758,48.742 U1.151
JIOA3: HDR1.9 U1.152 | length 15.8
  Bottom Layer w0.2: HDR1.9 18.1,59.3 17.3,58.5 17.3,55.5 15.3,53.5 15.3,50.8 16.858,49.242 U1.152
JIOB0: HDR1.83 U1.4 | length 14.6
  Bottom Layer w0.2: HDR1.83 47.7,58.1 52.2,53.6 52.2,51.15 50.792,49.742 U1.4
JIOB1: HDR1.85 U1.5 | length 15.2
  Bottom Layer w0.2: HDR1.85 48.5,57.9 52.6,53.8 52.6,50.975 50.867,49.242 U1.5
JIOB2: HDR1.87 U1.6 | length 15.7
  Bottom Layer w0.2: HDR1.87 49.3,57.684 53,53.984 53,50.8 50.942,48.742 U1.6
JIOB3: HDR1.89 U1.7 | length 16.3
  Bottom Layer w0.2: U1.7 51.017,48.242 53.4,50.625 53.4,54.15 50.1,57.45 HDR1.89
KBCLOCK: HDR1.22 U1.134 | length 59.1
  Bottom Layer w0.2: U1.134 17.48,40.242 3.9,53.822 3.9,67.175 9.575,72.85 18.775,72.85 22.9,68.725 HDR1.22
KBDATA: HDR1.24 U1.133 | length 61.5
  Bottom Layer w0.2: U1.133 17.414,39.742 3.5,53.656 3.5,67.375 9.4,73.275 19.092,73.275 23.7,68.667 HDR1.24
LCD_BCKL: HDR2.22 U1.94 | length 8.7
  Bottom Layer w0.2: HDR2.22 22.9,18.026 26.708,21.834 U1.94
LCD_E: HDR2.26 U1.89 | length 9
  Bottom Layer w0.2: HDR2.26 24.5,18.01 29.208,22.718 U1.89
LED0: HDR2.60 U1.62 | length 9
  Bottom Layer w0.2: HDR2.60 38.1,17.94 42.708,22.548 U1.62
LED1: HDR2.62 U1.61 | length 8.9
  Bottom Layer w0.2: HDR2.62 38.9,18.174 43.208,22.482 U1.61
LED2: HDR2.64 U1.60 | length 8.8
  Bottom Layer w0.2: HDR2.64 39.7,18.408 43.708,22.416 U1.60
LED3: HDR2.66 U1.59 | length 8.6
  Bottom Layer w0.2: HDR2.66 40.5,18.643 44.208,22.351 U1.59
LED4: HDR2.68 U1.58 | length 8.5
  Bottom Layer w0.2: HDR2.68 41.3,18.877 44.708,22.285 U1.58
LED5: HDR2.70 U1.57 | length 8.4
  Bottom Layer w0.2: HDR2.70@42.125,16.525 HDR2.70 42.1,19.111 45.208,22.219 U1.57
LED6: HDR2.72 U1.56 | length 8.3
  Bottom Layer w0.2: HDR2.72 42.9,19.346 45.708,22.154 U1.56
LED7: HDR2.74 U1.55 | length 8.1
  Bottom Layer w0.2: HDR2.74 43.7,19.58 46.208,22.088 U1.55
MOUSECLOCK: HDR1.26 U1.132 | length 63.8
  Bottom Layer w0.2: U1.132 17.348,39.242 3.1,53.491 3.1,67.575 9.2,73.675 19.55,73.675 24.5,68.725 HDR1.26
MOUSEDATA: HDR1.28 U1.129 | length 66.6
  Bottom Layer w0.2: U1.129@19.558,37.758 18.283,37.742 2.7,53.325 2.7,67.8 8.975,74.075 19.975,74.075 25.3,68.75 HDR1.28
NetLED1_1: LED1.1 R8.2 | length 2.2
  Top Layer w0.2: R8.2 LED1.1
NetLED1_2: LED1.2 U2.4 | length 2.7
  Top Layer w0.2: LED1.2@20.475,5.5 U2.4
NetLED2_1: LED2.1 R9.2 | length 2.2
  Top Layer w0.2: R9.2 LED2.1
NEXUS_TCK: HDR1.82 U1.9 | length 41.3
  Bottom Layer w0.2: HDR1.82 46.9,69.781 47.919,70.8 55.325,70.8 56.936,69.189 56.936,62.114 58.714,60.336 58.714,54.714 51.242,47.242 U1.9
NEXUS_TDI: HDR1.84 U1.8 | length 38.8
  Bottom Layer w0.2: HDR1.84 47.7,69.683 48.417,70.4 55.159,70.4 56.53,69.029 56.53,61.955 58.314,60.17 58.314,54.939 51.117,47.742 U1.8
NEXUS_TDO: HDR1.76 R5.1 | length 51.2
  Top Layer w0.5: R5.1 v1(55.05,49.35)
  Bottom Layer w0.2: HDR1.76 44.5,69.962 46.138,71.6 60.2,71.6 65.02,66.78 65.02,59.32 v1(55.05,49.35)
NEXUS_TDO#: R5.2 U1.11 | length 6
  Top Layer w0.5: v1(53.101,47.331) 53.101,45.591 R5.2
  Bottom Layer w0.2: U1.11 52.017,46.242 v1(53.101,47.331)
NEXUS_TMS: HDR1.80 U1.10 | length 50.9
  Bottom Layer w0.2: HDR1.80 46.1,69.845 47.455,71.2 60,71.2 64.62,66.58 64.62,60.02 51.342,46.742 U1.10
RAM0_DATA0: HDR2.42 U1.75 | length 9.6
  Bottom Layer w0.2: HDR2.42 30.9,17.688 31.587,18.375 32.044,18.375 36.208,22.539 U1.75
RAM0_DATA1: HDR2.40 U1.81 | length 8.4
  Bottom Layer w0.2: HDR2.40 30.1,19.25 33.208,22.358 U1.81
RAM0_DATA2: HDR2.38 U1.82 | length 8.5
  Bottom Layer w0.2: HDR2.38 29.3,19.016 32.708,22.424 U1.82
RAM0_DATA3: HDR2.36 U1.83 | length 8.6
  Bottom Layer w0.2: HDR2.36 28.5,18.781 32.208,22.489 U1.83
RAM0_DATA4: HDR2.34 U1.84 | length 8.8
  Bottom Layer w0.2: HDR2.34 27.7,18.66 31.708,22.668 U1.84
RAM0_DATA5: HDR2.32 U1.86 | length 8.7
  Bottom Layer w0.2: HDR2.32 26.9,18.58 30.708,22.388 U1.86
RAM0_DATA6: HDR2.30 U1.87 | length 8.8
  Bottom Layer w0.2: HDR2.30 26.1,18.425 30.208,22.533 U1.87
RAM0_DATA7: HDR2.28 U1.88 | length 8.9
  Bottom Layer w0.2: HDR2.28 25.3,18.234 29.708,22.642 U1.88
RAM0_OE: HDR1.41 U1.178 | length 7.6
  Bottom Layer w0.2: HDR1.41 30.9,57.482 32.208,56.174 U1.178
RAM0_WE: HDR1.79 U1.206 | length 8.6
  Bottom Layer w0.2: HDR1.79 46.1,59.675 44.4,57.975 44.4,56.86 46.208,55.052 U1.206
RAM1_DATA0: HDR1.45 U1.180 | length 7.4
  Bottom Layer w0.2: HDR1.45 32.5,57.013 33.208,56.305 U1.180
RAM1_DATA1: HDR1.49 U1.187 | length 8.2
  Bottom Layer w0.2: HDR1.49 34.1,58.675 36.708,56.067 U1.187
RAM1_DATA2: HDR1.53 U1.189 | length 7.9
  Bottom Layer w0.2: HDR1.53 35.7,58.206 37.708,56.198 U1.189
RAM1_DATA3: HDR1.57 U1.192 | length 7.9
  Bottom Layer w0.2: HDR1.57 37.3,57.738 39.208,55.83 U1.192
RAM1_DATA4: HDR1.55 U1.191 | length 8
  Bottom Layer w0.2: HDR1.55 36.5,57.972 38.708,55.764 U1.191
RAM1_DATA5: HDR1.51 U1.188 | length 8.1
  Bottom Layer w0.2: HDR1.51 34.9,58.441 37.208,56.133 U1.188
RAM1_DATA6: HDR1.47 U1.181 | length 7.3
  Bottom Layer w0.2: HDR1.47 33.3,56.779 33.708,56.371 U1.181
RAM1_DATA7: HDR1.43 U1.179 | length 7.5
  Bottom Layer w0.2: HDR1.43 31.7,57.247 32.708,56.239 U1.179
RAM1_OE: HDR1.39 U1.176 | length 7.6
  Bottom Layer w0.2: HDR1.39 30.1,57.716 31.208,56.608 U1.176
RAM1_WE: HDR1.61 U1.194 | length 7.6
  Bottom Layer w0.2: HDR1.61 38.9,57.269 40.208,55.961 U1.194
RAM_ADDR0: HDR1.21 U1.164 | length 8.1
  Bottom Layer w0.2: HDR1.21 22.9,57.362 25.208,55.054 U1.164
RAM_ADDR1: HDR1.25 U1.166 | length 7.8
  Bottom Layer w0.2: HDR1.25 24.5,56.894 26.208,55.186 U1.166
RAM_ADDR2: HDR1.29 U1.168 | length 7.6
  Bottom Layer w0.2: HDR1.29 26.1,56.425 27.208,55.317 U1.168
RAM_ADDR3: HDR1.33 U1.173 | length 7.9
  Bottom Layer w0.2: HDR1.33 27.7,58.419 29.708,56.411 U1.173
RAM_ADDR4: HDR1.65 U1.199 | length 8
  Bottom Layer w0.2: HDR1.65 40.5,56.8 42.708,54.592 U1.199
RAM_ADDR5: HDR1.69 U1.201 | length 7.8
  Bottom Layer w0.2: HDR1.69 42.1,56.332 43.708,54.724 U1.201
RAM_ADDR6: HDR1.73 U1.203 | length 8.2
  Bottom Layer w0.2: HDR1.73 43.7,59.45 42.9,58.65 42.9,56.663 44.708,54.855 U1.203
RAM_ADDR7: HDR1.77 U1.205 | length 8.5
  Bottom Layer w0.2: HDR1.77 45.3,59.55 43.875,58.125 43.875,56.82 45.708,54.987 U1.205
RAM_ADDR8: HDR1.75 U1.204 | length 8.4
  Bottom Layer w0.2: HDR1.75 44.5,59.575 43.3,58.375 43.3,56.829 45.208,54.921 U1.204
RAM_ADDR9: HDR1.71 U1.202 | length 8
  Bottom Layer w0.2: HDR1.71 42.9,59.425 42.5,59.025 42.5,56.498 44.208,54.79 U1.202
RAM_ADDR10: HDR1.67 U1.200 | length 7.9
  Bottom Layer w0.2: HDR1.67 41.3,56.566 43.208,54.658 U1.200
RAM_ADDR11: HDR1.63 U1.198 | length 8.1
  Bottom Layer w0.2: HDR1.63 39.7,57.035 42.208,54.527 U1.198
RAM_ADDR12: HDR1.59 U1.193 | length 7.8
  Bottom Layer w0.2: HDR1.59 38.1,57.503 39.708,55.895 U1.193
RAM_ADDR13: HDR1.35 U1.174 | length 7.8
  Bottom Layer w0.2: HDR1.35 28.5,58.185 30.208,56.477 U1.174
RAM_ADDR14: HDR1.31 U1.169 | length 7.4
  Bottom Layer w0.2: HDR1.31 26.9,56.191 27.708,55.383 U1.169
RAM_ADDR15: HDR1.27 U1.167 | length 7.7
  Bottom Layer w0.2: HDR1.27 25.3,56.659 26.708,55.251 U1.167
RAM_ADDR16: HDR1.23 U1.165 | length 7.9
  Bottom Layer w0.2: HDR1.23 23.7,57.128 25.708,55.12 U1.165
RAM_CS: HDR1.37 U1.175 | length 7.7
  Bottom Layer w0.2: HDR1.37 29.3,57.95 30.708,56.542 U1.175
RED0: HDR1.6 U1.146 | length 32.8
  Bottom Layer w0.2: HDR1.6 16.5,68.5 15.4,69.6 13.8,69.6 12.9,68.7 12.9,49.5 16.158,46.242 U1.146
RED1: HDR1.8 U1.145 | length 35.2
  Bottom Layer w0.2: HDR1.8 17.3,68.5 15.8,70 13.6,70 12.5,68.9 12.5,49.3 16.058,45.742 U1.145
REF_CLK: HDR2.4 U1.185 | length 64.4
  Top Layer w0.2: v1(19.375,23.8) 19.375,24.446 13.971,29.849 13.971,44.292 21.427,51.748 21.427,56.323 22.342,57.237 33.264,57.237 33.67,56.831 v1(34.864,56.831)
  Bottom Layer w0.2: HDR2.4 15.7,17.842 19.375,21.517 v1(19.375,23.8) ; v1(34.864,56.831) 35.708,55.986 U1.185
SCL: HDR2.5 U1.109 | length 29.4
  Bottom Layer w0.2: HDR2.5 16.5,8.5 15.3,7.3 13.6,7.3 12.6,8.3 12.6,10.3 12.9,10.6 12.9,15.6 12.6,15.9 12.6,22.2 18.142,27.742 U1.109
SDA: HDR2.3 U1.108 | length 27.1
  Bottom Layer w0.2: HDR2.3 15.7,8.4 15,7.7 13.8,7.7 13,8.5 13,10.1 13.3,10.4 13.3,15.8 13,16.1 13,22 18.242,27.242 U1.108
SPI_CLK: HDR1.46 U1.18 | length 76.8
  Bottom Layer w0.2: HDR1.46 32.5,72.3 35.6,75.4 58.8,75.4 66.62,67.58 66.62,57.995 51.367,42.742 U1.18
SPI_DIN: HDR1.44 U1.20 | length 79.3
  Bottom Layer w0.2: HDR1.44 31.7,72.1 35.4,75.8 59,75.8 67.02,67.78 67.02,57.83 50.933,41.742 U1.20
SPI_DOUT: HDR1.50 U1.16 | length 72.3
  Bottom Layer w0.2: HDR1.50 34.1,72.7 36,74.6 58.4,74.6 65.82,67.18 65.82,58.37 51.192,43.742 U1.16
SPI_MODE: HDR1.52 U1.15 | length 70.1
  Bottom Layer w0.2: HDR1.52 34.9,72.9 36.2,74.2 58.2,74.2 65.42,66.98 65.42,58.57 51.092,44.242 U1.15
SPI_SEL: HDR1.48 U1.17 | length 74.6
  Bottom Layer w0.2: HDR1.48 33.3,72.5 35.8,75 58.6,75 66.22,67.38 66.22,58.195 51.267,43.242 U1.17
SW0: HDR2.44 U1.74 | length 9.3
  Bottom Layer w0.2: HDR2.44 31.7,17.65 32.025,17.975 32.275,17.975 36.708,22.408 U1.74
SW1: HDR2.46 U1.73 | length 9
  Bottom Layer w0.2: HDR2.46 32.5,17.625 37.208,22.333 U1.73
SW2: HDR2.48 U1.71 | length 9.1
  Bottom Layer w0.2: HDR2.48 33.3,17.613 38.208,22.521 U1.71
SW3: HDR2.50 U1.70 | length 9
  Bottom Layer w0.2: HDR2.50 34.1,17.664 38.708,22.272 U1.70
SW4: HDR2.52 U1.69 | length 8.9
  Bottom Layer w0.2: HDR2.52 34.9,17.613 39.208,21.921 U1.69
SW5: HDR2.54 U1.68 | length 8.8
  Bottom Layer w0.2: HDR2.54 35.7,17.7 39.708,21.708 U1.68
SW6: HDR2.56 U1.64 | length 9.2
  Bottom Layer w0.2: HDR2.56 36.5,17.471 41.708,22.679 U1.64
SW7: HDR2.58 U1.63 | length 9.1
  Bottom Layer w0.2: HDR2.58 37.3,17.706 42.208,22.614 U1.63
SWC0: HDR2.18 U1.96 | length 8.9
  Bottom Layer w0.2: HDR2.18 21.3,17.557 25.708,21.965 U1.96
SWC1: HDR2.16 U1.97 | length 9.2
  Bottom Layer w0.2: HDR2.16 20.5,17.549 20.868,17.918 21.095,17.918 25.208,22.031 U1.97
SWC2: HDR2.14 U1.98 | length 9.5
  Bottom Layer w0.2: HDR2.14 19.7,17.683 20.335,18.318 20.929,18.318 24.708,22.097 U1.98
SWC3: HDR2.6 U1.102 | length 10.7
  Bottom Layer w0.2: HDR2.6 16.5,17.842 18.576,19.918 20.266,19.918 22.708,22.359 U1.102
SWR0: HDR2.20 U1.95 | length 8.8
  Bottom Layer w0.2: HDR2.20 22.1,17.792 26.208,21.9 U1.95
SWR1: HDR2.12 U1.99 | length 9.8
  Bottom Layer w0.2: HDR2.12 18.9,17.664 19.954,18.718 20.763,18.718 24.208,22.162 U1.99
SWR2: HDR2.10 U1.100 | length 10.1
  Bottom Layer w0.2: HDR2.10 18.1,17.771 19.447,19.118 20.598,19.118 23.708,22.228 U1.100
SWR3: HDR2.8 U1.101 | length 10.3
  Bottom Layer w0.2: HDR2.8 17.3,17.74 19.078,19.518 20.432,19.518 23.208,22.294 U1.101
TEST: HDR1.81 U1.3 | length 14
  Bottom Layer w0.2: HDR1.81 46.9,58.25 51.7,53.45 51.7,51.25 50.692,50.242 U1.3
VCC: C1.1 C3.1 C5.2 C6.2 C7.2 C8.2 C9.2 C10.2 C11.2 C12.2 C19.1 C20.1 C21.1 C22.1 C23.1 C24.1 C25.1 C26.1 C33.1 HDR1.34 HDR1.94 HDR1.96 HDR2.94 HDR2.96 R1.2 R6.2 R7.2 R8.1 R9.1 U1.13 U1.26 U1.38 U1.53 U1.66 U1.78 U1.91 U1.105 U1.118 U1.130 U1.143 U1.156 U1.171 U1.184 U1.196 U1.208 U2.5 | length 385
  Top Layer w0.25: R6.2 19.808,19.992 20.208,20.392 20.208,24.992 20.758,25.542 v1(21.508,25.542) ; R8.1 14.45,4.45 14.8,4.1 26.2,4.1 27.1,5 27.1,8.6 28.55,10.05 42.45,10.05 44.45,8.05 R9.1 ; U2.5 24.15,10.05 24.9,9.3 24.9,4.1 ; v1(27.701,69.505) 30.47,66.737 40.477,66.737 43.449,63.765 43.449,53.452 43.189,53.192 C7.2 ; 33.5,10.05 33.5,20.4 33,20.9 32.4,20.9 32.1,21.2 32.1,23.3 32.592,23.792 C24.1
  Top Layer w0.5: C12.2 21.108,31.342 ccw(c21.108,31.742) 21.508,31.742 v1(21.508,32.242) ; C11.2 21.108,39.142 cw(c21.108,38.742) 21.508,38.742 v1(21.508,38.242) ; C10.2 20.808,45.442 v1(21.508,44.742) ; C19.1 v1(21.508,25.542) ; v1(22.265,51.217) 22.9,51.852 C9.2 ; C23.1 27.508,24.842 v1(28.208,25.542) ; C5.2 28.008,52.142 v1(28.708,51.442) ; C24.1 33.608,25.142 34.008,25.542 v1(34.708,25.542) ; C6.2 34.308,51.842 ccw(c34.708,51.842) 34.708,51.442 v1(35.208,51.442) ; v1(40.708,25.542) 41.408,24.842 C25.1 ; v1(41.208,51.442) 41.708,51.442 ccw(c41.708,51.842) 42.108,51.842 C7.2 ; v1(47.408,25.542) 47.908,25.042 C26.1 ; v1(47.408,32.742) 47.408,32.242 ccw(c47.808,32.242) 47.808,31.842 C22.1 ; v1(47.408,38.742) 47.408,39.242 cw(c47.808,39.242) 47.808,39.642 C21.1 ; v1(47.408,45.242) 48.008,45.242 48.308,45.542 C20.1 ; v1(47.408,51.642) 47.908,52.142 C8.2
  Top Layer w1: v1@51.018,68.819 v1(51.275,69.075) v1(52.375,69.075)
  Top Layer w1.5: C1.1 30.608,46.492 ; 38.308,30.492 C3.1 ; v1(44.958,51.742) 44.958,55.098 48.75,58.89 48.75,66.55 v1@51.018,68.819 ; v1(47.708,28.692) 50.815,25.589 v1(50.815,18.502) ; v1(26.458,30.492) v1(26.458,46.492) v1(42.458,46.492) v1(42.458,30.492) v1(26.458,30.492)
  Bottom Layer w0.25: U1.105 20.608,25.742 20.808,25.542 v1(21.508,25.542) ; U1.118 v1(21.508,32.242) ; U1.130 v1(21.508,38.242) ; U1.143 v1(21.508,44.742) ; U1.156 21.96,51.242 v1(22.265,51.217) ; HDR1.34 v1(27.701,69.505) ; U1.91 v1(28.208,25.542) ; v1(28.708,51.442) U1.171 ; U1.78 v1(34.708,25.542) ; v1(35.208,51.442) U1.184 ; U1.66 v1(40.708,25.542) ; v1(41.208,51.442) U1.196 ; U1.53 47.208,24.642 47.408,24.842 v1(47.408,25.542) ; U1.208 47.208,52.442 47.408,52.242 v1(47.408,51.642) ; v1(47.408,32.742) U1.38 ; v1(47.408,38.742) U1.26 ; v1(47.408,45.242) U1.13 ; v1(50.815,18.502) 51.7,17.617 HDR2.94 ; v1(50.815,19.518) 52.5,17.833 HDR2.96 ; v1(51.275,69.075) 51.7,68.65 HDR1.94 ; v1(52.375,69.075) 52.5,68.95 HDR1.96
  Bottom Layer w0.5: v1(21.508,25.542) v1(26.458,30.492) ; v1(21.508,32.242) v1(26.458,32.242) ; v1(21.508,38.242) v1(26.458,38.242) ; v1(21.508,44.742) v1(26.458,44.742) ; v1(22.265,51.217) 22.265,49.871 25.644,46.492 v1(26.458,46.492) ; v1(28.208,25.542) v1(28.208,30.492) ; v1(28.708,46.492) v1(28.708,51.442) ; v1(34.708,25.542) v1(34.708,30.492) ; v1(35.208,46.492) v1(35.208,51.442) ; v1(40.708,25.542) v1(40.708,30.492) ; v1(41.208,46.492) v1(41.208,51.442) ; v1(42.458,32.742) v1(47.408,32.742) ; v1(42.458,38.742) v1(47.408,38.742) ; v1(42.458,45.242) v1(47.408,45.242) ; 43.808,30.492 43.808,29.142 v1(47.408,25.542) ; 44.958,50.233 45.999,50.233 v1(47.408,51.642)
  Bottom Layer w1.2: v1(42.458,30.492) 44.955,30.492 cw(c44.955,28.192) 46.582,29.819 v1(47.708,28.692) ; v1(42.458,46.492) 42.458,47.733 44.958,50.233 v1(44.958,51.742)
VCCINT: C2.1 C4.1 C13.2 C14.2 C15.2 C16.2 C17.2 C18.2 C27.1 C28.1 C29.1 C30.1 C31.1 C32.1 HDR1.93 HDR1.95 HDR2.93 HDR2.95 R2.1 U1.14 U1.28 U1.37 U1.67 U1.76 U1.90 U1.119 U1.128 U1.142 U1.172 U1.186 U1.195 | length 242.9
  Top Layer w0.5: C18.2 21.008,33.942 v1(21.508,33.442) ; C17.2 21.008,36.542 v1(21.508,37.042) ; C16.2 20.808,42.842 v1(21.508,43.542) ; v1(29.408,25.542) 30.108,24.842 C30.1 ; v1(29.908,51.442) 30.608,52.142 C13.2 ; v1(35.908,25.542) 35.908,24.942 36.208,24.642 C31.1 ; v1(36.408,51.442) 36.908,51.942 C14.2 ; C32.1 38.808,24.842 v1(39.508,25.542) ; C15.2 39.508,51.942 v1(40.008,51.442) ; v1(47.408,33.942) 47.908,34.442 C29.1 ; v1(47.408,37.542) 47.908,37.042 C28.1 ; v1(47.408,44.042) 47.408,43.342 47.808,42.942 C27.1
  Top Layer w1: v1@48.783,8.037 v1(49,7.8) v1(50.2,7.8) ; v1(52.95,58.45) 52.95,59.85 R2.1
  Top Layer w1.5: C4.1 v1(32.808,33.792) ; v1(36.108,43.192) C2.1 ; v1(44.208,25.242) 44.208,19.623 49,14.831 v1(49,7.8) ; v1(47.708,48.242) 49.72,48.242 52.95,51.473 v1(52.95,58.45) ; 24.708,28.742 44.208,28.742 44.208,48.242 24.708,48.242 24.708,28.742
  Bottom Layer w0.25: U1.119 20.808,32.742 v1(21.508,33.442) ; U1.128 20.608,37.242 20.808,37.042 v1(21.508,37.042) ; U1.142 20.808,44.242 v1(21.508,43.542) ; U1.90 28.708,24.842 v1(29.408,25.542) ; U1.172 29.208,52.142 v1(29.908,51.442) ; U1.76 35.708,24.642 35.908,24.842 v1(35.908,25.542) ; U1.186 36.208,52.342 36.408,52.142 v1(36.408,51.442) ; v1(39.508,25.542) 40.208,24.842 U1.67 ; v1(40.008,51.442) 40.708,52.142 U1.195 ; v1(47.408,33.942) 48.108,33.242 U1.37 ; v1(47.408,37.542) 48.108,37.542 48.308,37.742 U1.28 ; v1(47.408,44.042) 48.108,44.742 U1.14 ; v1(49,7.8) 49.65,8.425 51.525,8.425 51.7,8.6 HDR2.93 ; v1(50.2,7.8) 51.85,7.8 52.5,8.45 HDR2.95 ; 51.7,59.3 HDR1.93 51.7,58.575 52.75,57.525 v1(52.949,57.44) ; 52.5,59.425 HDR1.95 52.5,58.9 v1(52.95,58.45)
  Bottom Layer w0.5: v1(21.508,33.442) v1(24.708,33.442) ; v1(21.508,37.042) v1(24.708,37.042) ; v1(21.508,43.542) v1(24.708,43.542) ; v1(29.408,25.542) v1(29.408,28.742) ; v1(29.908,48.242) v1(29.908,51.442) ; v1(35.908,25.542) v1(35.908,28.742) ; v1(36.408,48.242) v1(36.408,51.442) ; v1(39.508,25.542) v1(39.508,28.742) ; v1(40.008,48.242) v1(40.008,51.442) ; v1(44.208,33.942) v1(47.408,33.942) ; v1(44.208,37.542) v1(47.408,37.542) ; v1(44.208,44.042) v1(47.408,44.042)
  Bottom Layer w1.2: v1(42.358,28.742) 44.208,26.892 v1(44.208,25.242) ; v1(44.175,46.625) 45.05,47.525 47,47.525 v1(47.708,48.242)
  Bottom Layer w1.5: v1(32.808,28.742) v1(32.808,33.792) ; v1(36.108,43.192) 38.108,45.192 v1(38.108,48.242)
VDRIVE: HDR1.20 U1.135 | length 56.7
  Bottom Layer w0.2: U1.135 17.545,40.742 4.3,53.988 4.3,66.975 9.75,72.425 18.325,72.425 22.1,68.65 HDR1.20
VREF: HDR1.91 R2.2 R3.1 | length 13.4
  Top Layer w0.5: v1(55,56.775) R2.2@55,60.5 ; R2.2 R3.1
  Bottom Layer w0.25: HDR1.91 50.9,58.117 52.568,56.45 54.675,56.45 v1(55,56.775)
pads on no net: HDR1.86 HDR1.88 HDR1.90 HDR1.92 HDR1.MH1 HDR1.MH2 HDR1.MH3 HDR1.MH4 HDR1.MH5 HDR1.MH6 HDR2.76 HDR2.78 HDR2.79 HDR2.80 HDR2.81 HDR2.82 HDR2.83 HDR2.84 HDR2.85 HDR2.86 HDR2.87 HDR2.88 HDR2.89 HDR2.90 HDR2.91 HDR2.92 HDR2.MH1 HDR2.MH2 HDR2.MH3 HDR2.MH4 HDR2.MH5 HDR2.MH6 U1.FID1 U1.FID2 U2.1

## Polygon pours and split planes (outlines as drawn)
GND on Top Layer "Top Layer-GND" (solid, remove dead copper, pour order 1000): 69.057,81.057 69.081,81 69.081,0 69.057,-0.057 69,-0.081 0,-0.081 -0.057,-0.057 -0.081,0 -0.081,81 -0.057,81.057 0,81.081 69,81.081
GND on Bottom Layer "Bottom Layer-GND" (solid, remove dead copper, pour order 1001): 69.057,81.057 69.081,81 69.081,0 69.057,-0.057 69,-0.081 0,-0.081 -0.057,-0.057 -0.081,0 -0.081,81 -0.057,81.057 0,81.081 69,81.081

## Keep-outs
Keep-Out Layer:
  the board outline again, w0.8

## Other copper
Bottom Layer:
  text "1" at 48.908,51.892 h1 r270

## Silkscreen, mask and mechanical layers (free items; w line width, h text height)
Bottom Overlay:
  drawing of 850 lines, arcs and shapes, not listed
  text "REV 1.02" at 47.6,76.5 h1.3
  text "NBP1" at 54.5,76.5 h1.3
  text "1" at 13.97,58.42 h1
  text "1" at 13.462,7.493 h1
PCB Boundary:
  the board outline again, w0.25
  text "PCB boundary coincides with centre-line of tracks" at 0,-12 h0.75
Gerber ID:
  text ".Layer_Name" at 0,-6 h0.75
Printout ID:
  text ".Printout_Name" at 0,-10 h0.75
Drill Drawing:
  text ".Legend" at 0,-8 h0.75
